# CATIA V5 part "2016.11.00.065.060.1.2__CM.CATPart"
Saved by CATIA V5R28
Part number: 2016.11.00.065.060.1.2__CM
Property "id_number": "2016.11.00.065.060.1.2"
Publications: "Absolute Axis System", "driver", "slider", "base", "cam diagram"
Bounding box of the stored display mesh (mm): x -60 to 190, y -65 to 65, z 0 to 220
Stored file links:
  N:\B2\Normteile\K\2016\11-14\006\cm\2016.11.00.065.060.1.2__CM.CATPart
  H:\CAD_Startmodelle\Tests\fill-in_PRT-SL_TEMPLATE.xlsx
  H:\CAD_Startmodelle\V5-R24\R24_TEMPLATE_PRT_FIBRO_CAM_TECNOLOGIES_INDEX.xlsx
  H:\z_Einordnen\170511__Anfrage_TK_HN\170511__CC01_TKHN.CATPart
  N:\B2\Normteile\K\2016\9xxx\2016.9024.1705.001\Entwurf_\170511__CC01_TKHN.CATPart
  N:\B2\Normteile\K\2016\9xxx\2016.9024.1707.006\Konstruktion\2016.9024.1707.006__HP__CUSTOMIZED_CAM_CM.CATPart
  N:\B2\Normteile\K\2016\9xxx\2016.9024.1707.005\Konstruktion\2016.9024.1707.005__HP__CUSTOMIZED_CAM_CM.CATPart
  N:\B2\Normteile\K\2016\9xxx\2016.9024.1707.008\Konstruktion\2016.9024.1707.008__HP__CUSTOMIZED_CAM_CM.CATPart
  N:\B2\Normteile\K\2016\9xxx\2016.9024.1707.009\Konstruktion\2016.9024.1707.009__HP__CUSTOMIZED_CAM_CM.CATPart
  N:\B2\Normteile\K\2016\9xxx\2016.9024.1707.010\Konstruktion\2016.9024.1707.010__HP__CUSTOMIZED_CAM_CM.CATPart
  N:\B2\Normteile\K\2016\9xxx\2016.9024.1708.002\Konstruktion\2016.9024.1708.002__HP__CUSTOMIZED_CAM_CM.CATPart
  N:\B2\Normteile\K\2016\9xxx\2016.9024.1802.001\Konstruktion\2016.9024.1802.001__HP__CUSTOMIZED_CAM_CM.CATPart
  N:\B2\Normteile\K\2016\9xxx\2016.9024.1802.002\Konstruktion\2016.9024.1802.002__HP__CUSTOMIZED_CAM_CM.CATPart
  N:\B2\Normteile\K\2016\9xxx\2016.9024.1811.003\Konstruktion\2016.9024.1811.003__HP__CUSTOMIZED_CAM_CM.CATPart
  N:\B2\Normteile\K\2016\9xxx\2016.9015.1811.001\Konstruktion\am\2016.9015.1811.001__AM__FCC_HV_DMC_0125-00.CATPart
  N:\B2\Normteile\K\2016\9xxx\2016.9024.1811.009\Konstruktion\2016.9024.1811.009__HP__CUSTOMIZED_CAM_CM.CATPart
  N:\B2\Normteile\K\2016\9xxx\2016.9024.1911.002\Konstruktion\am\2016.9024.1911.002__AM__CUSTOMIZED_CAM_CM.CATPart
  N:\B2\Normteile\K\2016\9xxx\2016.9024.2002.006\Konstruktion\2016.9024.2002.006__AM.CATPart
  N:\B2\Normteile\K\2016\9xxx\2016.9024.2004.001\Konstruktion\2016.9024.2004.001__AM__FCC_HV_CAEC_0260-45.CATPart
  N:\B2\Normteile\K\2016\9xxx\2016.9024.2006.002\Konstruktion\2016.9024.2006.002__AM__FCC_HV_CAEC_0260-40.CATPart
  N:\B2\Normteile\K\2016\9xxx\2016.9024.2006.005\Konstruktion\am\2016.9024.2006.005__AM__CFCC_HV_AEPC_0080-65.CATPart
  N:\B2\Normteile\K\2016\9xxx\2016.9024.2006.004\Konstruktion\am\2016.9024.2006.004__AM__CFCC_HV_AEC_0210-35.CATPart
  N:\B2\Normteile\K\2016\9xxx\2016.9026.2006.001\Konstruktion\am\2016.9026.2006.001__AM__FCC_LV_CAEC_0180-40.CATPart
  N:\B2\Normteile\K\2016\9xxx\2016.9015.2007.001\Konstruktion\am\2016.9015.2007.001__AM__FCC_HV_CDMPC_0090-00.CATPart
  N:\B2\Normteile\K\2016\9xxx\2016.9024.2005.001\Konstruktion\am\2016.9024.2005.001__AM__CFCC_HV_AEPC_1400-70.CATPart
  N:\B2\Normteile\K\2016\9xxx\2016.9024.2007.004\Konstruktion\am\2016.9024.2007.004__AM__CFCC_HV_AEC_1250-80.CATPart
  N:\B2\Normteile\K\2016\11-14\005\2016.11.00.052.040.1.02__AS__DIE_MOUNT_CAM__W52_A0_S40.CATProduct
  N:\B2\Normteile\K\2016\11-14\cm\005\catia\2016.11.00.052.025.1.2__CM.CATPart
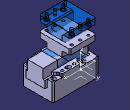
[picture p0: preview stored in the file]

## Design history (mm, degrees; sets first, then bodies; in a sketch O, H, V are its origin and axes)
Parameters
  group "process_parameters"
    modeltype = ""
    stocklist = ""
    id_number = "2016.11.00.065.060.1.2"
    id_number_rough_part = ""
    revision_index = ""
    revision_date = ""
    revision_description = ""
    category = ""
    material = ""
    manufacturing_information = ""
    standard = ""
  group "release_parameters_startmodel"
    sm_revision_index = "2016_00" {design table}
    sm_revision_date = "20.08.2016" {design table}
    sm_revision_name = "Meyer" {design table}
    sm_revision_description = "new part template FIBRO cam tecnologies" {design table}
AxisSystem1: origin (0, 0, 0), X (1, 0, 0), Y (0, 1, 0), Z (0, 0, 1)
Set1 "reference elements"
  Sketch1 "cam diagram" on ZX plane of AxisSystem1, origin (0, 0, 0), H (-1, 0, 0), V (0, 0, 1)
    line L1 (0, 0) -> (60, 0)
    line L2 (60, 0) -> (0, 60)
    point P2 (0, 60)
    line L3 (0, 60) -> (0, 0)
    length L1 = 60
    angle H L2 = 45
    horizontal: L1 H
    coincidence: P2 V
    vertical: L3 V
Body1 "finished_part" (main body)
  Body2 "rough_part"
  Add1 "rough_part": tool Body2
  Body3 "milling operations"
  Remove1 "milling operations": tool Body3
  Body4 "drilling operations"
  Remove2 "drilling operations": tool Body4
Body5 "driver"
  Solid1: solid without history
Body6 "slider"
  Solid2: solid without history
Body7 "base"
  Solid3: solid without history
Body8 "opened position"
  Body9 "slider"
    Body10 "slider"
      Solid4: linked copy from another document
    Assemble1: tool Body10
    Translate1: FirstPoint vertex [element of Sketch1 | element of Sketch1], SecondPoint vertex [element of Sketch1 | element of Sketch1], ToTransfor Assemble1
  Assemble2: tool Body9
  Body11 "driver"
    Body12 "driver"
      Solid5: linked copy from another document
    Assemble3: tool Body12
    Translate2: FirstPoint vertex [element of Sketch1 | element of Sketch1], SecondPoint vertex [element of Sketch1 | element of Sketch1], ToTransfor Assemble3
  Assemble4: tool Body11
